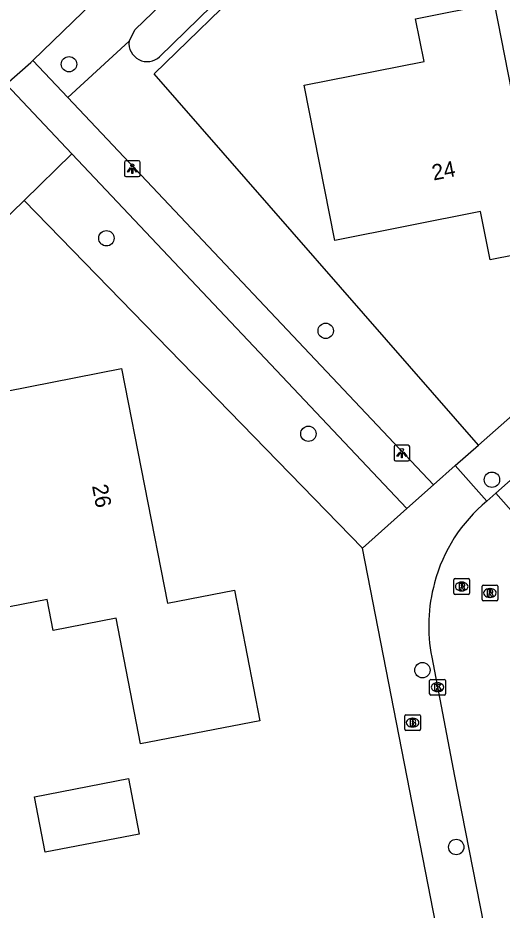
# Model space of a CAD drawing. Extents: x 157663 to 158496, y 379212 to 380934.
# Drawn here: x 158204 to 158234.8, y 380348.2 to 380405 of the extents above; entities that cross this region are included whole.
import ezdxf

# ---------------------------------------------------------------- set-up
doc = ezdxf.new("R2010")
doc.units = 0
for name, color, linetype in [('IMGEO_Berm_groen', 7, 'Continuous'), ('IMGEO_Boom', 7, 'Continuous'), ('IMGEO_Brandkraan', 7, 'Continuous'), ('IMGEO_Groenvoorziening', 7, 'Continuous'), ('IMGEO_Kolk', 7, 'Continuous'), ('IMGEO_Lichtpunt', 7, 'Continuous'), ('IMGEO_Pand', 7, 'Continuous'), ('IMGEO_Pand_nummerreeks', 7, 'Continuous'), ('IMGEO_Rijbaan_lokaal_gesloten', 7, 'Continuous'), ('IMGEO_Rijbaan_lokaal_open', 7, 'Continuous'), ('IMGEO_Rioolput', 7, 'Continuous'), ('IMGEO_Voetpad_open', 7, 'Continuous'), ('IMGEO_Waterloop', 7, 'Continuous')]:
    doc.layers.add(name, color=color, linetype=linetype)

msp = doc.modelspace()

# ---------------------------------------------------------------- linework, layer by layer
at = {"layer": 'IMGEO_Berm_groen'}
for points in [[(158207.208, 380399.961), (158211.102, 380403.546)], [(158204.422, 380393.396), (158207.47, 380396.36)], [(158204.422, 380393.396), (158178.774, 380368.449)]]:
    msp.add_lwpolyline(points, dxfattribs=at)
at = {"layer": 'IMGEO_Boom'}
for centre in [(158207.283, 380402.074), (158209.66, 380390.996), (158223.613, 380385.104), (158222.511, 380378.551), (158234.19, 380375.627), (158229.766, 380363.503), (158231.917, 380352.248)]:
    msp.add_circle(centre, 0.489, dxfattribs=at)
at = {"layer": 'IMGEO_Brandkraan'}
for p, q in [((158228.639, 380359.742), (158228.639, 380360.594)), ((158228.714, 380360.668), (158229.566, 380360.668)), ((158229.127, 380360.448), (158229.152, 380360.448)), ((158229.64, 380360.594), (158229.64, 380359.742)), ((158229.566, 380359.668), (158228.714, 380359.668)), ((158229.15, 380359.888), (158229.125, 380359.888))]:
    msp.add_line(p, q, dxfattribs=at)
for points in [[(158228.639, 380359.742), (158228.639, 380360.594)], [(158228.714, 380360.668), (158229.566, 380360.668)], [(158228.987, 380360.368), (158228.987, 380359.968), (158229.2, 380359.968)], [(158229.218, 380360.368), (158228.987, 380360.368)], [(158229.166, 380360.287), (158229.112, 380360.287), (158229.112, 380360.211)], [(158229.112, 380360.211), (158229.165, 380360.211)], [(158229.174, 380360.135), (158229.112, 380360.135), (158229.112, 380360.054)], [(158229.64, 380360.594), (158229.64, 380359.742)], [(158229.566, 380359.668), (158228.714, 380359.668)], [(158229.112, 380360.054), (158229.174, 380360.054)]]:
    msp.add_lwpolyline(points, dxfattribs=at)
for centre, radius, start, end in [((158228.716, 380360.592), 0.0765, 91.552, 178.448), ((158228.716, 380360.592), 0.0765, 91.552, 178.448), ((158229.167, 380360.249), 0.0379, 267.8285, 90.9355), ((158229.175, 380360.094), 0.0404, 269.8759, 90.5077), ((158229.222, 380360.223), 0.145, 59.4692, 91.5367), ((158229.247, 380360.27), 0.0922, 285.5137, 58.1501), ((158229.252, 380360.078), 0.105, 301.3115, 78.989), ((158229.564, 380360.592), 0.0765, 1.552, 88.448), ((158229.564, 380360.592), 0.0765, 1.552, 88.448), ((158228.716, 380359.744), 0.0765, 181.552, 268.448), ((158228.716, 380359.744), 0.0765, 181.552, 268.448), ((158229.206, 380360.219), 0.251, 268.6676, 293.5347), ((158229.564, 380359.744), 0.0765, 271.552, 358.448), ((158229.564, 380359.744), 0.0765, 271.552, 358.448)]:
    msp.add_arc(centre, radius, start, end, dxfattribs=at)
for centre, major_axis, ratio, start_param, end_param in [((158229.126, 380360.168), (-0.387, 0.002), 0.722429, 4.712389, 7.853982), ((158229.151, 380360.168), (-0.39, 0.002), 0.717154, 1.570796, 4.712389)]:
    msp.add_ellipse(centre, major_axis=major_axis, ratio=ratio, start_param=start_param, end_param=end_param, dxfattribs=at)
at = {"layer": 'IMGEO_Groenvoorziening'}
for points in [[(158233.333, 380377.826), (158212.706, 380401.465), (158276.529, 380463.435)], [(158225.952, 380371.26), (158204.422, 380393.396)]]:
    msp.add_lwpolyline(points, dxfattribs=at)
at = {"layer": 'IMGEO_Kolk'}
for p, q in [((158230.226, 380361.994), (158230.226, 380362.846)), ((158230.301, 380362.92), (158231.153, 380362.92)), ((158230.714, 380362.7), (158230.739, 380362.7)), ((158231.227, 380362.846), (158231.227, 380361.994)), ((158231.153, 380361.92), (158230.301, 380361.92)), ((158230.737, 380362.14), (158230.712, 380362.14))]:
    msp.add_line(p, q, dxfattribs=at)
for points in [[(158230.226, 380361.994), (158230.226, 380362.846)], [(158230.301, 380362.92), (158231.153, 380362.92)], [(158230.547, 380362.62), (158230.67, 380362.62), (158230.67, 380362.469), (158230.8, 380362.62), (158230.964, 380362.62), (158230.818, 380362.469), (158230.971, 380362.22), (158230.819, 380362.22), (158230.734, 380362.384), (158230.67, 380362.317), (158230.67, 380362.22), (158230.547, 380362.22), (158230.547, 380362.62)], [(158231.227, 380362.846), (158231.227, 380361.994)], [(158231.153, 380361.92), (158230.301, 380361.92)]]:
    msp.add_lwpolyline(points, dxfattribs=at)
for centre, start, end in [((158230.303, 380362.844), 91.552, 178.448), ((158230.303, 380362.844), 91.552, 178.448), ((158231.151, 380362.844), 1.552, 88.448), ((158231.151, 380362.844), 1.552, 88.448), ((158230.303, 380361.996), 181.552, 268.448), ((158230.303, 380361.996), 181.552, 268.448), ((158231.151, 380361.996), 271.552, 358.448), ((158231.151, 380361.996), 271.552, 358.448)]:
    msp.add_arc(centre, 0.0765, start, end, dxfattribs=at)
for centre, major_axis, ratio, start_param, end_param in [((158230.713, 380362.42), (-0.387, 0.002), 0.722429, 4.712389, 7.853982), ((158230.738, 380362.42), (-0.39, 0.002), 0.717154, 1.570796, 4.712389)]:
    msp.add_ellipse(centre, major_axis=major_axis, ratio=ratio, start_param=start_param, end_param=end_param, dxfattribs=at)
at = {"layer": 'IMGEO_Lichtpunt'}
for p, q in [((158211.713, 380395.922), (158210.905, 380395.922)), ((158211.713, 380395.922), (158210.905, 380395.922)), ((158210.811, 380395.827), (158210.811, 380395.02)), ((158210.811, 380395.827), (158210.811, 380395.02)), ((158211.807, 380395.02), (158211.807, 380395.827)), ((158211.807, 380395.02), (158211.807, 380395.827)), ((158210.905, 380394.926), (158211.713, 380394.926)), ((158210.905, 380394.926), (158211.713, 380394.926)), ((158228.861, 380377.821), (158228.053, 380377.821)), ((158228.861, 380377.821), (158228.053, 380377.821)), ((158227.959, 380377.726), (158227.959, 380376.919)), ((158227.959, 380377.726), (158227.959, 380376.919)), ((158228.955, 380376.919), (158228.955, 380377.726)), ((158228.955, 380376.919), (158228.955, 380377.726)), ((158228.053, 380376.825), (158228.861, 380376.825)), ((158228.053, 380376.825), (158228.861, 380376.825))]:
    msp.add_line(p, q, dxfattribs=at)
for points in [[(158211.185, 380395.491), (158211.224, 380395.463), (158211.036, 380395.201), (158210.998, 380395.228), (158211.185, 380395.491)], [(158211.287, 380395.443), (158211.334, 380395.443), (158211.334, 380395.121), (158211.287, 380395.121), (158211.287, 380395.443)], [(158211.397, 380395.463), (158211.435, 380395.49), (158211.622, 380395.228), (158211.583, 380395.2), (158211.397, 380395.463)], [(158228.333, 380377.39), (158228.372, 380377.362), (158228.184, 380377.1), (158228.146, 380377.127), (158228.333, 380377.39)], [(158228.435, 380377.342), (158228.482, 380377.342), (158228.482, 380377.02), (158228.435, 380377.02), (158228.435, 380377.342)], [(158228.545, 380377.362), (158228.583, 380377.389), (158228.77, 380377.127), (158228.731, 380377.099), (158228.545, 380377.362)]]:
    msp.add_lwpolyline(points, dxfattribs=at)
for centre in [(158211.31, 380395.625), (158228.458, 380377.524)]:
    msp.add_circle(centre, 0.0994, dxfattribs=at)
for centre, start, end in [((158210.905, 380395.827), 90, 180), ((158210.905, 380395.827), 90, 180), ((158211.713, 380395.827), 0, 90), ((158211.713, 380395.827), 0, 90), ((158210.905, 380395.02), 180, 270), ((158210.905, 380395.02), 180, 270), ((158211.713, 380395.02), 270, 0), ((158211.713, 380395.02), 270, 360), ((158228.053, 380377.726), 90, 180), ((158228.053, 380377.726), 90, 180), ((158228.861, 380377.726), 0, 90), ((158228.861, 380377.726), 0, 90), ((158228.053, 380376.919), 180, 270), ((158228.053, 380376.919), 180, 270), ((158228.861, 380376.919), 270, 0), ((158228.861, 380376.919), 270, 360)]:
    msp.add_arc(centre, 0.0946, start, end, dxfattribs=at)
at = {"layer": 'IMGEO_Pand'}
for points in [[(158237.414, 380390.287), (158234.076, 380389.629), (158233.471, 380392.692), (158224.197, 380390.862), (158222.248, 380400.737), (158229.867, 380402.241), (158229.329, 380404.968), (158234.322, 380405.953), (158237.414, 380390.287)], [(158199.546, 380366.777), (158199.181, 380368.648), (158198.28, 380373.27), (158197.432, 380373.105), (158197.349, 380373.533), (158196.392, 380378.44), (158202.057, 380379.544), (158201.778, 380380.977), (158210.627, 380382.702), (158213.539, 380367.762), (158217.803, 380368.593), (158219.423, 380360.284), (158211.84, 380358.806), (158210.279, 380366.815), (158206.284, 380366.036), (158205.903, 380368), (158199.546, 380366.777)], [(158205.772, 380351.91), (158205.084, 380355.444), (158211.062, 380356.608), (158211.75, 380353.074), (158205.772, 380351.91)]]:
    msp.add_lwpolyline(points, dxfattribs=at)
at = {"layer": 'IMGEO_Rijbaan_lokaal_gesloten'}
for points in [[(158204.985, 380402.319), (158277.006, 380471.994)], [(158203.283, 380400.795), (158204.847, 380402.186), (158204.985, 380402.319)]]:
    msp.add_lwpolyline(points, dxfattribs=at)
at = {"layer": 'IMGEO_Rijbaan_lokaal_open'}
for points in [[(158290.558, 380424.363), (158280.432, 380415.427), (158277.036, 380412.427), (158268.418, 380404.808), (158265.005, 380401.815), (158264.255, 380401.144), (158260.861, 380398.145), (158251.843, 380390.163), (158248.452, 380387.176), (158240.599, 380380.224), (158237.209, 380377.235), (158234.426, 380374.771)], [(158233.855, 380374.265), (158234.426, 380374.771)], [(158234.426, 380374.771), (158238.294, 380370.403)], [(158230.358, 380364.334), (158230.96, 380361.209), (158231.812, 380356.752), (158238.265, 380323.802)]]:
    msp.add_lwpolyline(points, dxfattribs=at)
for centre, radius, start, end in [((158240.377, 380366.443), 10.184, 129.8242, 165.1124), ((158240.556, 380366.318), 10.389, 164.699, 191.0113)]:
    msp.add_arc(centre, radius, start, end, dxfattribs=at)
at = {"layer": 'IMGEO_Rioolput'}
for p, q in [((158231.766, 380368.404), (158231.766, 380369.256)), ((158231.841, 380369.33), (158232.693, 380369.33)), ((158232.767, 380369.256), (158232.767, 380368.404)), ((158232.254, 380369.11), (158232.279, 380369.11)), ((158233.558, 380367.994), (158233.558, 380368.846)), ((158233.633, 380368.92), (158234.485, 380368.92)), ((158234.046, 380368.7), (158234.071, 380368.7)), ((158234.559, 380368.846), (158234.559, 380367.994)), ((158232.693, 380368.33), (158231.841, 380368.33)), ((158232.277, 380368.55), (158232.252, 380368.55)), ((158234.069, 380368.14), (158234.044, 380368.14)), ((158234.485, 380367.92), (158233.633, 380367.92))]:
    msp.add_line(p, q, dxfattribs=at)
for points in [[(158231.766, 380368.404), (158231.766, 380369.256)], [(158231.841, 380369.33), (158232.693, 380369.33)], [(158232.767, 380369.256), (158232.767, 380368.404)], [(158232.355, 380369.028), (158232.103, 380369.03), (158232.103, 380368.63)], [(158232.103, 380368.63), (158232.227, 380368.63), (158232.227, 380368.792), (158232.238, 380368.792)], [(158232.281, 380368.949), (158232.227, 380368.949), (158232.227, 380368.868)], [(158232.227, 380368.868), (158232.279, 380368.868)], [(158232.285, 380368.763), (158232.356, 380368.63), (158232.496, 380368.63), (158232.431, 380368.756)], [(158233.558, 380367.994), (158233.558, 380368.846)], [(158233.633, 380368.92), (158234.485, 380368.92)], [(158234.559, 380368.846), (158234.559, 380367.994)], [(158232.693, 380368.33), (158231.841, 380368.33)], [(158234.147, 380368.618), (158233.895, 380368.62), (158233.895, 380368.22)], [(158233.895, 380368.22), (158234.019, 380368.22), (158234.019, 380368.382), (158234.03, 380368.382)], [(158234.073, 380368.539), (158234.019, 380368.539), (158234.019, 380368.458)], [(158234.019, 380368.458), (158234.071, 380368.458)], [(158234.077, 380368.353), (158234.148, 380368.22), (158234.288, 380368.22), (158234.223, 380368.346)], [(158234.485, 380367.92), (158233.633, 380367.92)]]:
    msp.add_lwpolyline(points, dxfattribs=at)
for centre, radius, start, end in [((158231.843, 380369.254), 0.0765, 91.552, 178.448), ((158231.843, 380369.254), 0.0765, 91.552, 178.448), ((158232.691, 380369.254), 0.0765, 1.552, 88.448), ((158232.691, 380369.254), 0.0765, 1.552, 88.448), ((158232.237, 380368.739), 0.0533, 26.0293, 88.6989), ((158232.263, 380369.057), 0.19, 274.7715, 282.9687), ((158232.287, 380368.853), 0.0964, 77.0061, 93.1865), ((158232.301, 380368.91), 0.0378, 276.6634, 79.6772), ((158232.354, 380368.918), 0.109, 350.3612, 89.416), ((158232.352, 380368.918), 0.112, 277.5842, 350.9817), ((158232.336, 380368.703), 0.108, 29.5134, 73.7905), ((158233.635, 380368.844), 0.0765, 91.552, 178.448), ((158233.635, 380368.844), 0.0765, 91.552, 178.448), ((158234.483, 380368.844), 0.0765, 1.552, 88.448), ((158234.483, 380368.844), 0.0765, 1.552, 88.448), ((158231.843, 380368.406), 0.0765, 181.552, 268.448), ((158231.843, 380368.406), 0.0765, 181.552, 268.448), ((158232.691, 380368.406), 0.0765, 271.552, 358.448), ((158232.691, 380368.406), 0.0765, 271.552, 358.448), ((158234.029, 380368.329), 0.0533, 26.0293, 88.6989), ((158234.055, 380368.647), 0.19, 274.7715, 282.9687), ((158234.079, 380368.443), 0.0964, 77.0061, 93.1865), ((158234.093, 380368.5), 0.0378, 276.6634, 79.6772), ((158234.146, 380368.508), 0.109, 350.3612, 89.416), ((158234.144, 380368.508), 0.112, 277.5842, 350.9817), ((158234.128, 380368.293), 0.108, 29.5134, 73.7905), ((158233.635, 380367.996), 0.0765, 181.552, 268.448), ((158233.635, 380367.996), 0.0765, 181.552, 268.448), ((158234.483, 380367.996), 0.0765, 271.552, 358.448), ((158234.483, 380367.996), 0.0765, 271.552, 358.448)]:
    msp.add_arc(centre, radius, start, end, dxfattribs=at)
for centre, major_axis, ratio, start_param, end_param in [((158232.253, 380368.83), (-0.387, 0.002), 0.722429, 4.712389, 7.853982), ((158232.278, 380368.83), (-0.39, 0.002), 0.717154, 1.570796, 4.712389), ((158234.045, 380368.42), (-0.387, 0.002), 0.722429, 4.712389, 7.853982), ((158234.07, 380368.42), (-0.39, 0.002), 0.717154, 1.570796, 4.712389)]:
    msp.add_ellipse(centre, major_axis=major_axis, ratio=ratio, start_param=start_param, end_param=end_param, dxfattribs=at)
at = {"layer": 'IMGEO_Voetpad_open'}
for points in [[(158292.091, 380429.371), (158279.605, 380418.293), (158279.393, 380418.507), (158278.773, 380417.976), (158275.266, 380414.885), (158268.406, 380408.809), (158233.333, 380377.826)], [(158204.985, 380402.319), (158207.208, 380399.961)], [(158207.47, 380396.36), (158203.283, 380400.795)], [(158207.208, 380399.961), (158230.468, 380375.295)], [(158207.47, 380396.36), (158228.777, 380373.794)], [(158231.859, 380376.524), (158233.333, 380377.826)], [(158230.468, 380375.295), (158231.859, 380376.524)], [(158231.859, 380376.524), (158233.855, 380374.265)], [(158228.777, 380373.794), (158230.468, 380375.295)], [(158228.777, 380373.794), (158225.952, 380371.26)], [(158233.293, 380333.634), (158225.952, 380371.26)]]:
    msp.add_lwpolyline(points, dxfattribs=at)
at = {"layer": 'IMGEO_Waterloop'}
for points in [[(158211.102, 380403.546), (158211.489, 380404.284), (158273.239, 380463.746)], [(158274.391, 380462.382), (158213.049, 380402.542)]]:
    msp.add_lwpolyline(points, dxfattribs=at)
msp.add_arc((158212.263, 380403.408), 1.169, 173.2347, 312.2081, dxfattribs=at)

# ---------------------------------------------------------------- texts
at = {"layer": 'IMGEO_Pand_nummerreeks'}
for s, rotation, p in [('24', 11.1625, (158230.474, 380394.669)), ('26', 281.0292, (158208.74, 380375.239))]:
    msp.add_text(s, height=1, rotation=rotation, dxfattribs=at).set_placement(p)

doc.saveas('drawing.dxf')
